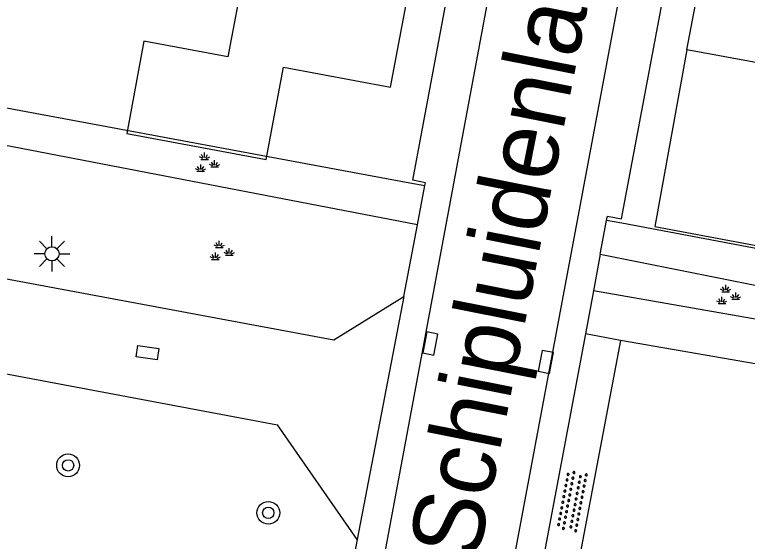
# Model space of a CAD drawing. Extents: x 124000 to 128010, y 398999 to 403000.
# Drawn here: x 126599.41 to 126625.21, y 399541.58 to 399560.13 of the extents above; entities that cross this region are included whole.
import ezdxf

# ---------------------------------------------------------------- set-up
doc = ezdxf.new("R2010")
doc.units = 0
for name, color, linetype in [('gg-afsc-hekwerk', 7, 'Continuous'), ('gg-anno-openbare ruimte label', 7, 'Continuous'), ('gg-bbg-bijgebouw', 7, 'Continuous'), ('gg-bbg-luifel en loopbrug', 7, 'Continuous'), ('gg-knt-verharding', 7, 'Continuous'), ('gt-grn-groengrens', 7, 'Continuous'), ('gt-grn-weggrens', 7, 'Continuous'), ('gt-symb-boom', 7, 'Continuous'), ('gt-symb-groenvak', 7, 'Continuous'), ('gt-symb-kolk', 7, 'Continuous'), ('gt-symb-kolk center center', 7, 'Continuous'), ('gt-symb-lichtmast', 7, 'Continuous'), ('gt-symb-overige verharding', 7, 'Continuous')]:
    doc.layers.add(name, color=color, linetype=linetype)

# ---------------------------------------------------------------- blocks, each defined once
blk = doc.blocks.new('gt0-BOOM')
at = {"layer": 'gt-symb-boom'}
for radius in [0.4, 0.2]:
    blk.add_circle((0, 0), radius, dxfattribs=at)
blk = doc.blocks.new('gt0-OVH')
at = {"layer": 'gt-symb-overige verharding'}
for points in [[(-0.972, 0.298), (-0.967, 0.308), (-0.965, 0.319), (-0.966, 0.33), (-0.971, 0.34), (-0.978, 0.348), (-0.988, 0.353), (-0.999, 0.355), (-1.01, 0.354), (-1.02, 0.349), (-1.028, 0.342), (-1.033, 0.332), (-1.035, 0.321), (-1.034, 0.31), (-1.029, 0.3), (-1.022, 0.292), (-1.012, 0.287), (-1.001, 0.285), (-0.99, 0.286), (-0.98, 0.291)], [(-0.772, 0.298), (-0.767, 0.308), (-0.765, 0.319), (-0.766, 0.33), (-0.771, 0.34), (-0.778, 0.348), (-0.788, 0.353), (-0.799, 0.355), (-0.81, 0.354), (-0.82, 0.349), (-0.828, 0.342), (-0.833, 0.332), (-0.835, 0.321), (-0.834, 0.31), (-0.829, 0.3), (-0.822, 0.292), (-0.812, 0.287), (-0.801, 0.285), (-0.79, 0.286), (-0.78, 0.291)], [(-0.572, 0.298), (-0.567, 0.308), (-0.565, 0.319), (-0.566, 0.33), (-0.571, 0.34), (-0.578, 0.348), (-0.588, 0.353), (-0.599, 0.355), (-0.61, 0.354), (-0.62, 0.349), (-0.628, 0.342), (-0.633, 0.332), (-0.635, 0.321), (-0.634, 0.31), (-0.629, 0.3), (-0.622, 0.292), (-0.612, 0.287), (-0.601, 0.285), (-0.59, 0.286), (-0.58, 0.291)], [(-0.372, 0.298), (-0.367, 0.308), (-0.365, 0.319), (-0.366, 0.33), (-0.371, 0.34), (-0.378, 0.348), (-0.388, 0.353), (-0.399, 0.355), (-0.41, 0.354), (-0.42, 0.349), (-0.428, 0.342), (-0.433, 0.332), (-0.435, 0.321), (-0.434, 0.31), (-0.429, 0.3), (-0.422, 0.292), (-0.412, 0.287), (-0.401, 0.285), (-0.39, 0.286), (-0.38, 0.291)], [(-0.172, 0.298), (-0.167, 0.308), (-0.165, 0.319), (-0.166, 0.33), (-0.171, 0.34), (-0.178, 0.348), (-0.188, 0.353), (-0.199, 0.355), (-0.21, 0.354), (-0.22, 0.349), (-0.228, 0.342), (-0.233, 0.332), (-0.235, 0.321), (-0.234, 0.31), (-0.229, 0.3), (-0.222, 0.292), (-0.212, 0.287), (-0.201, 0.285), (-0.19, 0.286), (-0.18, 0.291)], [(0.028, 0.298), (0.033, 0.308), (0.035, 0.319), (0.034, 0.33), (0.029, 0.34), (0.022, 0.348), (0.012, 0.353), (0.001, 0.355), (-0.01, 0.354), (-0.02, 0.349), (-0.028, 0.342), (-0.033, 0.332), (-0.035, 0.321), (-0.034, 0.31), (-0.029, 0.3), (-0.022, 0.292), (-0.012, 0.287), (-0.001, 0.285), (0.01, 0.286), (0.02, 0.291)], [(0.228, 0.298), (0.233, 0.308), (0.235, 0.319), (0.234, 0.33), (0.229, 0.34), (0.222, 0.348), (0.212, 0.353), (0.201, 0.355), (0.19, 0.354), (0.18, 0.349), (0.172, 0.342), (0.167, 0.332), (0.165, 0.321), (0.166, 0.31), (0.171, 0.3), (0.178, 0.292), (0.188, 0.287), (0.199, 0.285), (0.21, 0.286), (0.22, 0.291)], [(0.428, 0.298), (0.433, 0.308), (0.435, 0.319), (0.434, 0.33), (0.429, 0.34), (0.422, 0.348), (0.412, 0.353), (0.401, 0.355), (0.39, 0.354), (0.38, 0.349), (0.372, 0.342), (0.367, 0.332), (0.365, 0.321), (0.366, 0.31), (0.371, 0.3), (0.378, 0.292), (0.388, 0.287), (0.399, 0.285), (0.41, 0.286), (0.42, 0.291)], [(0.628, 0.298), (0.633, 0.308), (0.635, 0.319), (0.634, 0.33), (0.629, 0.34), (0.622, 0.348), (0.612, 0.353), (0.601, 0.355), (0.59, 0.354), (0.58, 0.349), (0.572, 0.342), (0.567, 0.332), (0.565, 0.321), (0.566, 0.31), (0.571, 0.3), (0.578, 0.292), (0.588, 0.287), (0.599, 0.285), (0.61, 0.286), (0.62, 0.291)], [(0.828, 0.298), (0.833, 0.308), (0.835, 0.319), (0.834, 0.33), (0.829, 0.34), (0.822, 0.348), (0.812, 0.353), (0.801, 0.355), (0.79, 0.354), (0.78, 0.349), (0.772, 0.342), (0.767, 0.332), (0.765, 0.321), (0.766, 0.31), (0.771, 0.3), (0.778, 0.292), (0.788, 0.287), (0.799, 0.285), (0.81, 0.286), (0.82, 0.291)], [(1.028, 0.298), (1.033, 0.308), (1.035, 0.319), (1.034, 0.33), (1.029, 0.34), (1.022, 0.348), (1.012, 0.353), (1.001, 0.355), (0.99, 0.354), (0.98, 0.349), (0.972, 0.342), (0.967, 0.332), (0.965, 0.321), (0.966, 0.31), (0.971, 0.3), (0.978, 0.292), (0.988, 0.287), (0.999, 0.285), (1.01, 0.286), (1.02, 0.291)], [(-0.872, 0.106), (-0.867, 0.116), (-0.865, 0.126), (-0.866, 0.137), (-0.871, 0.147), (-0.878, 0.156), (-0.888, 0.161), (-0.899, 0.163), (-0.91, 0.162), (-0.92, 0.157), (-0.928, 0.15), (-0.933, 0.14), (-0.935, 0.129), (-0.934, 0.118), (-0.929, 0.108), (-0.922, 0.1), (-0.912, 0.095), (-0.901, 0.092), (-0.89, 0.094), (-0.88, 0.098)], [(-0.672, 0.106), (-0.667, 0.116), (-0.665, 0.126), (-0.666, 0.137), (-0.671, 0.147), (-0.678, 0.156), (-0.688, 0.161), (-0.699, 0.163), (-0.71, 0.162), (-0.72, 0.157), (-0.728, 0.15), (-0.733, 0.14), (-0.735, 0.129), (-0.734, 0.118), (-0.729, 0.108), (-0.722, 0.1), (-0.712, 0.095), (-0.701, 0.092), (-0.69, 0.094), (-0.68, 0.098)], [(-0.472, 0.106), (-0.467, 0.116), (-0.465, 0.126), (-0.466, 0.137), (-0.471, 0.147), (-0.478, 0.156), (-0.488, 0.161), (-0.499, 0.163), (-0.51, 0.162), (-0.52, 0.157), (-0.528, 0.15), (-0.533, 0.14), (-0.535, 0.129), (-0.534, 0.118), (-0.529, 0.108), (-0.522, 0.1), (-0.512, 0.095), (-0.501, 0.092), (-0.49, 0.094), (-0.48, 0.098)], [(-0.272, 0.106), (-0.267, 0.116), (-0.265, 0.126), (-0.266, 0.137), (-0.271, 0.147), (-0.278, 0.156), (-0.288, 0.161), (-0.299, 0.163), (-0.31, 0.162), (-0.32, 0.157), (-0.328, 0.15), (-0.333, 0.14), (-0.335, 0.129), (-0.334, 0.118), (-0.329, 0.108), (-0.322, 0.1), (-0.312, 0.095), (-0.301, 0.092), (-0.29, 0.094), (-0.28, 0.098)], [(-0.072, 0.106), (-0.067, 0.116), (-0.065, 0.126), (-0.066, 0.137), (-0.071, 0.147), (-0.078, 0.156), (-0.088, 0.161), (-0.099, 0.163), (-0.11, 0.162), (-0.12, 0.157), (-0.128, 0.15), (-0.133, 0.14), (-0.135, 0.129), (-0.134, 0.118), (-0.129, 0.108), (-0.122, 0.1), (-0.112, 0.095), (-0.101, 0.092), (-0.09, 0.094), (-0.08, 0.098)], [(0.128, 0.106), (0.133, 0.116), (0.135, 0.126), (0.134, 0.137), (0.129, 0.147), (0.122, 0.156), (0.112, 0.161), (0.101, 0.163), (0.09, 0.162), (0.08, 0.157), (0.072, 0.15), (0.067, 0.14), (0.065, 0.129), (0.066, 0.118), (0.071, 0.108), (0.078, 0.1), (0.088, 0.095), (0.099, 0.092), (0.11, 0.094), (0.12, 0.098)], [(0.328, 0.106), (0.333, 0.116), (0.335, 0.126), (0.334, 0.137), (0.329, 0.147), (0.322, 0.156), (0.312, 0.161), (0.301, 0.163), (0.29, 0.162), (0.28, 0.157), (0.272, 0.15), (0.267, 0.14), (0.265, 0.129), (0.266, 0.118), (0.271, 0.108), (0.278, 0.1), (0.288, 0.095), (0.299, 0.092), (0.31, 0.094), (0.32, 0.098)], [(0.528, 0.106), (0.533, 0.116), (0.535, 0.126), (0.534, 0.137), (0.529, 0.147), (0.522, 0.156), (0.512, 0.161), (0.501, 0.163), (0.49, 0.162), (0.48, 0.157), (0.472, 0.15), (0.467, 0.14), (0.465, 0.129), (0.466, 0.118), (0.471, 0.108), (0.478, 0.1), (0.488, 0.095), (0.499, 0.092), (0.51, 0.094), (0.52, 0.098)], [(0.728, 0.106), (0.733, 0.116), (0.735, 0.126), (0.734, 0.137), (0.729, 0.147), (0.722, 0.156), (0.712, 0.161), (0.701, 0.163), (0.69, 0.162), (0.68, 0.157), (0.672, 0.15), (0.667, 0.14), (0.665, 0.129), (0.666, 0.118), (0.671, 0.108), (0.678, 0.1), (0.688, 0.095), (0.699, 0.092), (0.71, 0.094), (0.72, 0.098)], [(0.928, 0.106), (0.933, 0.116), (0.935, 0.126), (0.934, 0.137), (0.929, 0.147), (0.922, 0.156), (0.912, 0.161), (0.901, 0.163), (0.89, 0.162), (0.88, 0.157), (0.872, 0.15), (0.867, 0.14), (0.865, 0.129), (0.866, 0.118), (0.871, 0.108), (0.878, 0.1), (0.888, 0.095), (0.899, 0.092), (0.91, 0.094), (0.92, 0.098)], [(-0.972, -0.142), (-0.967, -0.132), (-0.965, -0.121), (-0.966, -0.11), (-0.971, -0.1), (-0.978, -0.092), (-0.988, -0.087), (-0.999, -0.085), (-1.01, -0.086), (-1.02, -0.091), (-1.028, -0.098), (-1.033, -0.108), (-1.035, -0.119), (-1.034, -0.13), (-1.029, -0.14), (-1.022, -0.148), (-1.012, -0.153), (-1.001, -0.155), (-0.99, -0.154), (-0.98, -0.149)], [(-0.772, -0.142), (-0.767, -0.132), (-0.765, -0.121), (-0.766, -0.11), (-0.771, -0.1), (-0.778, -0.092), (-0.788, -0.087), (-0.799, -0.085), (-0.81, -0.086), (-0.82, -0.091), (-0.828, -0.098), (-0.833, -0.108), (-0.835, -0.119), (-0.834, -0.13), (-0.829, -0.14), (-0.822, -0.148), (-0.812, -0.153), (-0.801, -0.155), (-0.79, -0.154), (-0.78, -0.149)], [(-0.572, -0.142), (-0.567, -0.132), (-0.565, -0.121), (-0.566, -0.11), (-0.571, -0.1), (-0.578, -0.092), (-0.588, -0.087), (-0.599, -0.085), (-0.61, -0.086), (-0.62, -0.091), (-0.628, -0.098), (-0.633, -0.108), (-0.635, -0.119), (-0.634, -0.13), (-0.629, -0.14), (-0.622, -0.148), (-0.612, -0.153), (-0.601, -0.155), (-0.59, -0.154), (-0.58, -0.149)], [(-0.372, -0.142), (-0.367, -0.132), (-0.365, -0.121), (-0.366, -0.11), (-0.371, -0.1), (-0.378, -0.092), (-0.388, -0.087), (-0.399, -0.085), (-0.41, -0.086), (-0.42, -0.091), (-0.428, -0.098), (-0.433, -0.108), (-0.435, -0.119), (-0.434, -0.13), (-0.429, -0.14), (-0.422, -0.148), (-0.412, -0.153), (-0.401, -0.155), (-0.39, -0.154), (-0.38, -0.149)], [(-0.172, -0.142), (-0.167, -0.132), (-0.165, -0.121), (-0.166, -0.11), (-0.171, -0.1), (-0.178, -0.092), (-0.188, -0.087), (-0.199, -0.085), (-0.21, -0.086), (-0.22, -0.091), (-0.228, -0.098), (-0.233, -0.108), (-0.235, -0.119), (-0.234, -0.13), (-0.229, -0.14), (-0.222, -0.148), (-0.212, -0.153), (-0.201, -0.155), (-0.19, -0.154), (-0.18, -0.149)], [(0.028, -0.142), (0.033, -0.132), (0.035, -0.121), (0.034, -0.11), (0.029, -0.1), (0.022, -0.092), (0.012, -0.087), (0.001, -0.085), (-0.01, -0.086), (-0.02, -0.091), (-0.028, -0.098), (-0.033, -0.108), (-0.035, -0.119), (-0.034, -0.13), (-0.029, -0.14), (-0.022, -0.148), (-0.012, -0.153), (-0.001, -0.155), (0.01, -0.154), (0.02, -0.149)], [(0.228, -0.142), (0.233, -0.132), (0.235, -0.121), (0.234, -0.11), (0.229, -0.1), (0.222, -0.092), (0.212, -0.087), (0.201, -0.085), (0.19, -0.086), (0.18, -0.091), (0.172, -0.098), (0.167, -0.108), (0.165, -0.119), (0.166, -0.13), (0.171, -0.14), (0.178, -0.148), (0.188, -0.153), (0.199, -0.155), (0.21, -0.154), (0.22, -0.149)], [(0.428, -0.142), (0.433, -0.132), (0.435, -0.121), (0.434, -0.11), (0.429, -0.1), (0.422, -0.092), (0.412, -0.087), (0.401, -0.085), (0.39, -0.086), (0.38, -0.091), (0.372, -0.098), (0.367, -0.108), (0.365, -0.119), (0.366, -0.13), (0.371, -0.14), (0.378, -0.148), (0.388, -0.153), (0.399, -0.155), (0.41, -0.154), (0.42, -0.149)], [(0.628, -0.142), (0.633, -0.132), (0.635, -0.121), (0.634, -0.11), (0.629, -0.1), (0.622, -0.092), (0.612, -0.087), (0.601, -0.085), (0.59, -0.086), (0.58, -0.091), (0.572, -0.098), (0.567, -0.108), (0.565, -0.119), (0.566, -0.13), (0.571, -0.14), (0.578, -0.148), (0.588, -0.153), (0.599, -0.155), (0.61, -0.154), (0.62, -0.149)], [(0.828, -0.142), (0.833, -0.132), (0.835, -0.121), (0.834, -0.11), (0.829, -0.1), (0.822, -0.092), (0.812, -0.087), (0.801, -0.085), (0.79, -0.086), (0.78, -0.091), (0.772, -0.098), (0.767, -0.108), (0.765, -0.119), (0.766, -0.13), (0.771, -0.14), (0.778, -0.148), (0.788, -0.153), (0.799, -0.155), (0.81, -0.154), (0.82, -0.149)], [(1.028, -0.142), (1.033, -0.132), (1.035, -0.121), (1.034, -0.11), (1.029, -0.1), (1.022, -0.092), (1.012, -0.087), (1.001, -0.085), (0.99, -0.086), (0.98, -0.091), (0.972, -0.098), (0.967, -0.108), (0.965, -0.119), (0.966, -0.13), (0.971, -0.14), (0.978, -0.148), (0.988, -0.153), (0.999, -0.155), (1.01, -0.154), (1.02, -0.149)], [(-0.872, -0.334), (-0.867, -0.324), (-0.865, -0.314), (-0.866, -0.303), (-0.871, -0.293), (-0.878, -0.284), (-0.888, -0.279), (-0.899, -0.277), (-0.91, -0.278), (-0.92, -0.283), (-0.928, -0.29), (-0.933, -0.3), (-0.935, -0.311), (-0.934, -0.322), (-0.929, -0.332), (-0.922, -0.34), (-0.912, -0.345), (-0.901, -0.348), (-0.89, -0.346), (-0.88, -0.342)], [(-0.672, -0.334), (-0.667, -0.324), (-0.665, -0.314), (-0.666, -0.303), (-0.671, -0.293), (-0.678, -0.284), (-0.688, -0.279), (-0.699, -0.277), (-0.71, -0.278), (-0.72, -0.283), (-0.728, -0.29), (-0.733, -0.3), (-0.735, -0.311), (-0.734, -0.322), (-0.729, -0.332), (-0.722, -0.34), (-0.712, -0.345), (-0.701, -0.348), (-0.69, -0.346), (-0.68, -0.342)], [(-0.472, -0.334), (-0.467, -0.324), (-0.465, -0.314), (-0.466, -0.303), (-0.471, -0.293), (-0.478, -0.284), (-0.488, -0.279), (-0.499, -0.277), (-0.51, -0.278), (-0.52, -0.283), (-0.528, -0.29), (-0.533, -0.3), (-0.535, -0.311), (-0.534, -0.322), (-0.529, -0.332), (-0.522, -0.34), (-0.512, -0.345), (-0.501, -0.348), (-0.49, -0.346), (-0.48, -0.342)], [(-0.272, -0.334), (-0.267, -0.324), (-0.265, -0.314), (-0.266, -0.303), (-0.271, -0.293), (-0.278, -0.284), (-0.288, -0.279), (-0.299, -0.277), (-0.31, -0.278), (-0.32, -0.283), (-0.328, -0.29), (-0.333, -0.3), (-0.335, -0.311), (-0.334, -0.322), (-0.329, -0.332), (-0.322, -0.34), (-0.312, -0.345), (-0.301, -0.348), (-0.29, -0.346), (-0.28, -0.342)], [(-0.072, -0.334), (-0.067, -0.324), (-0.065, -0.314), (-0.066, -0.303), (-0.071, -0.293), (-0.078, -0.284), (-0.088, -0.279), (-0.099, -0.277), (-0.11, -0.278), (-0.12, -0.283), (-0.128, -0.29), (-0.133, -0.3), (-0.135, -0.311), (-0.134, -0.322), (-0.129, -0.332), (-0.122, -0.34), (-0.112, -0.345), (-0.101, -0.348), (-0.09, -0.346), (-0.08, -0.342)], [(0.128, -0.334), (0.133, -0.324), (0.135, -0.314), (0.134, -0.303), (0.129, -0.293), (0.122, -0.284), (0.112, -0.279), (0.101, -0.277), (0.09, -0.278), (0.08, -0.283), (0.072, -0.29), (0.067, -0.3), (0.065, -0.311), (0.066, -0.322), (0.071, -0.332), (0.078, -0.34), (0.088, -0.345), (0.099, -0.348), (0.11, -0.346), (0.12, -0.342)], [(0.328, -0.334), (0.333, -0.324), (0.335, -0.314), (0.334, -0.303), (0.329, -0.293), (0.322, -0.284), (0.312, -0.279), (0.301, -0.277), (0.29, -0.278), (0.28, -0.283), (0.272, -0.29), (0.267, -0.3), (0.265, -0.311), (0.266, -0.322), (0.271, -0.332), (0.278, -0.34), (0.288, -0.345), (0.299, -0.348), (0.31, -0.346), (0.32, -0.342)], [(0.528, -0.334), (0.533, -0.324), (0.535, -0.314), (0.534, -0.303), (0.529, -0.293), (0.522, -0.284), (0.512, -0.279), (0.501, -0.277), (0.49, -0.278), (0.48, -0.283), (0.472, -0.29), (0.467, -0.3), (0.465, -0.311), (0.466, -0.322), (0.471, -0.332), (0.478, -0.34), (0.488, -0.345), (0.499, -0.348), (0.51, -0.346), (0.52, -0.342)], [(0.728, -0.334), (0.733, -0.324), (0.735, -0.314), (0.734, -0.303), (0.729, -0.293), (0.722, -0.284), (0.712, -0.279), (0.701, -0.277), (0.69, -0.278), (0.68, -0.283), (0.672, -0.29), (0.667, -0.3), (0.665, -0.311), (0.666, -0.322), (0.671, -0.332), (0.678, -0.34), (0.688, -0.345), (0.699, -0.348), (0.71, -0.346), (0.72, -0.342)], [(0.928, -0.334), (0.933, -0.324), (0.935, -0.314), (0.934, -0.303), (0.929, -0.293), (0.922, -0.284), (0.912, -0.279), (0.901, -0.277), (0.89, -0.278), (0.88, -0.283), (0.872, -0.29), (0.867, -0.3), (0.865, -0.311), (0.866, -0.322), (0.871, -0.332), (0.878, -0.34), (0.888, -0.345), (0.899, -0.348), (0.91, -0.346), (0.92, -0.342)]]:
    blk.add_lwpolyline(points, close=True, dxfattribs=at)
blk = doc.blocks.new('gt0-KOLK')
at = {"layer": 'gt-symb-kolk'}
blk.add_lwpolyline([(0, 0), (0.375, 0), (0.375, 0.4), (-0.375, 0.4), (-0.375, 0), (0, 0)], dxfattribs=at)
blk = doc.blocks.new('gt0-KOLKCC')
at = {"layer": 'gt-symb-kolk center center'}
blk.add_lwpolyline([(-0.375, 0.2), (0.375, 0.2), (0.375, -0.2), (-0.375, -0.2)], close=True, dxfattribs=at)
blk = doc.blocks.new('gt0-GRVAK')
at = {"layer": 'gt-symb-groenvak'}
for p, q in [((-0.091, 0.211), (-0.156, 0.322)), ((-0.047, 0.214), (-0.047, 0.393)), ((-0.004, 0.211), (0.061, 0.322)), ((-0.11, 0.189), (-0.228, 0.24)), ((-0.182, 0.153), (0.088, 0.153)), ((0.015, 0.189), (0.133, 0.24)), ((0.262, -0.052), (0.197, 0.059)), ((0.305, -0.049), (0.305, 0.13)), ((0.349, -0.052), (0.414, 0.059)), ((-0.245, -0.228), (-0.363, -0.177)), ((-0.226, -0.206), (-0.291, -0.095)), ((-0.183, -0.203), (-0.183, -0.024)), ((-0.139, -0.206), (-0.074, -0.095)), ((-0.12, -0.228), (-0.002, -0.177)), ((0.243, -0.074), (0.125, -0.023)), ((0.17, -0.11), (0.441, -0.11)), ((0.368, -0.074), (0.486, -0.023)), ((-0.318, -0.264), (-0.047, -0.264))]:
    blk.add_line(p, q, dxfattribs=at)
blk = doc.blocks.new('gt0-LMAST')
at = {"layer": 'gt-symb-lichtmast'}
for p, q in [((-0.005, 0.246), (-0.005, 0.621)), ((-0.182, 0.173), (-0.447, 0.438)), ((0.172, 0.173), (0.437, 0.438)), ((-0.255, -0.004), (-0.63, -0.004)), ((-0.182, -0.181), (-0.447, -0.446)), ((-0.005, -0.254), (-0.005, -0.629)), ((0.437, -0.446), (0.172, -0.181)), ((0.245, -0.004), (0.62, -0.004))]:
    blk.add_line(p, q, dxfattribs=at)
blk.add_circle((-0.005, -0.004), 0.25, dxfattribs=at)

msp = doc.modelspace()

# ---------------------------------------------------------------- linework, layer by layer
at = {"layer": 'gg-afsc-hekwerk'}
for p, q in [((126596.957, 399557.246), (126613.331, 399554.214)), ((126637.112, 399549.734), (126620.788, 399552.785))]:
    msp.add_line(p, q, dxfattribs=at)
at = {"layer": 'gg-bbg-bijgebouw'}
for p, q in [((126623.087, 399558.895), (126623.649, 399561.912)), ((126629.03, 399557.789), (126623.087, 399558.895))]:
    msp.add_line(p, q, dxfattribs=at)
at = {"layer": 'gg-bbg-luifel en loopbrug'}
for points in [[(126607.49, 399561.685), (126606.922, 399558.643), (126603.965, 399559.195), (126603.358, 399555.943), (126608.269, 399555.028), (126608.875, 399558.278), (126612.645, 399557.574), (126613.226, 399560.614)], [(126623.087, 399558.895), (126621.959, 399552.671), (126628.845, 399551.383), (126629.977, 399557.613), (126629.03, 399557.789)]]:
    msp.add_lwpolyline(points, dxfattribs=at)
at = {"layer": 'gg-knt-verharding'}
for p, q in [((126613.597, 399552.735), (126613.858, 399554.116)), ((126567.752, 399553.353), (126608.674, 399545.688)), ((126620.034, 399551.695), (126620.257, 399552.884)), ((126613.12, 399550.209), (126613.597, 399552.735)), ((126620.034, 399551.695), (126619.793, 399550.405)), ((126619.793, 399550.405), (126619.509, 399548.887)), ((126632.812, 399548.13), (126619.793, 399550.405)), ((126619.509, 399548.887), (126617.343, 399537.318)), ((126620.742, 399548.656), (126619.509, 399548.887)), ((126620.742, 399548.656), (126618.564, 399537.138)), ((126632.593, 399546.611), (126620.742, 399548.656)), ((126611.468, 399541.647), (126608.674, 399545.688)), ((126611.468, 399541.647), (126610.911, 399538.541))]:
    msp.add_line(p, q, dxfattribs=at)
for points in [[(126604.782, 399500), (126618.345, 399572.783), (126616.938, 399573.052)], [(126613.858, 399554.116), (126613.875, 399554.205), (126613.437, 399554.309), (126616.875, 399572.714)], [(126609.329, 399500), (126622.802, 399571.943), (126624.304, 399571.678)], [(126620.257, 399552.884), (126620.285, 399553.034), (126620.781, 399552.937), (126624.243, 399571.352)], [(126595.969, 399551.421), (126610.653, 399548.675), (126613.12, 399550.209)]]:
    msp.add_lwpolyline(points, dxfattribs=at)
at = {"layer": 'gt-grn-groengrens'}
for p, q in [((126613.331, 399554.214), (126613.858, 399554.116)), ((126620.788, 399552.785), (126620.257, 399552.884))]:
    msp.add_line(p, q, dxfattribs=at)
for points in [[(126613.597, 399552.735), (126596.767, 399555.975), (126596.88, 399556.822)], [(126620.034, 399551.695), (126637.22, 399548.256), (126637.43, 399549.245)]]:
    msp.add_lwpolyline(points, dxfattribs=at)
at = {"layer": 'gt-grn-weggrens'}
msp.add_line((126613.12, 399550.209), (126611.468, 399541.647), dxfattribs=at)

# ---------------------------------------------------------------- block references
at = {"layer": 'gt-symb-boom'}
for p in [(126601.293, 399544.26), (126608.345, 399542.588)]:
    msp.add_blockref('gt0-BOOM', p, dxfattribs=at)
at = {"layer": 'gt-symb-groenvak'}
for p in [(126606.147, 399554.883), (126606.664, 399551.775), (126624.499, 399550.219)]:
    msp.add_blockref('gt0-GRVAK', p, dxfattribs=at)
at = {"layer": 'gt-symb-kolk'}
for p, rotation in [((126613.853, 399548.588), -100.54573436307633), ((126618.314, 399547.868), 79.39794170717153)]:
    msp.add_blockref('gt0-KOLK', p, dxfattribs=dict(at, rotation=rotation))
at = {"layer": 'gt-symb-kolk center center', "rotation": 171.8374905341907}
msp.add_blockref('gt0-KOLKCC', (126604.089, 399548.232), dxfattribs=at)
at = {"layer": 'gt-symb-lichtmast'}
msp.add_blockref('gt0-LMAST', (126600.73, 399551.712), dxfattribs=at)
at = {"layer": 'gt-symb-overige verharding', "rotation": -100.71464389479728}
msp.add_blockref('gt0-OVH', (126619.04, 399543), dxfattribs=at)

# ---------------------------------------------------------------- texts
at = {"layer": 'gg-anno-openbare ruimte label'}
msp.add_text('Schipluidenlaan', height=2.5, rotation=78.8, dxfattribs=at).set_placement((126615.722, 399540.862))

doc.saveas('drawing.dxf')
